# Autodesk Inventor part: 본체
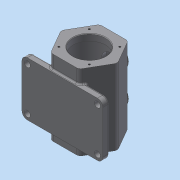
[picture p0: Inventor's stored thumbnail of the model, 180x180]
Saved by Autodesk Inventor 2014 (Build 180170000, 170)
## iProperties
Created: 2021-06
Part Number: 본체
Material: 일반
Document SubType Name: Modeling
Designer: net
Density: 1 g/cm^3
Appearance: 기본값
Author: net
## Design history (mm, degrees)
sketch "스케치2" dims "d3" = 105
  geometry: L1 (-52.5, 0)-(-26.25, 45.466); L2 (-26.25, 45.466)-(26.25, 45.466); L3 (26.25, 45.466)-(52.5, 0); L4 (52.5, 0)-(26.25, -45.466); L5 (26.25, -45.466)-(-26.25, -45.466); L6 (-26.25, -45.466)-(-52.5, 0); 4 further points
  constraints: 12 end point, 2 coincident, 1 horizontal alignment, 1 midpoint, 1 vertical alignment, 15 other
extrude "돌출1" new body sketch "스케치2" stored distance "d4" = 140; taper "d5" = 0 deg
node "작업 평면1"
sketch "스케치3"
  geometry: L1 (75, 45)-(-75, 45); L2 (-75, 45)-(-75, -55); L3 (-75, -55)-(75, -55); L4 (75, -55)-(75, 45); L5 (26.25, 70)-(52.5, 70) reference; L6 (52.5, -70)-(26.25, -70) reference; 2 further points
  constraints: 8 end point, 2 parallel, 1 horizontal, 1 midpoint, 1 perpendicular, 1 vertical alignment
  dimensions: "d7" = 25 distance between parallel lines of L1 L5; "d8" = 15 distance between parallel lines of L6 L3; "d9" = 150 distance between parallel lines of L2 L4
extrude "돌출2" join sketch "스케치3" distance "d10" = 12; taper "d11" = 0 deg
fillet "모깎기1" dims "d12" = 10
sketch "스케치4"
  geometry: C1 r 5.5 at (-65, 45); C2 r 5.5 at (-65, -35); A1 r 10 centre (-65, 45) between (-65, 55) and (-75, 45) reference; A2 r 10 centre (-65, -35) between (-75, -35) and (-65, -45) reference; 1 further point
  constraints: 2 centre point, 2 coincident
  dimensions: "d13" = 11 diameter of C1; "d14" = 11 diameter of C2
extrude "돌출3" cut sketch "스케치4" stored distance "d15" = 12; taper "d16" = 0 deg
sketch "스케치5"
  geometry: L1 (45.466, 70)-(0, 70) reference; L2 (0, 70)-(-45.466, 70) reference; L3 (-45.466, 70)-(0, 70) reference; L4 (0, 70)-(45.466, 70) reference; L5 (0, -70)-(45.466, -70) reference; L6 (45.466, -70)-(0, -70) reference; L7 (0, -70)-(-45.466, -70) reference; L8 (-45.466, -70)-(0, -70) reference; L9 (0, 70)-(30, 70); L10 (30, 58)-(37.5, 58); L11 (37.5, 58)-(37.5, -58); L12 (37.5, -58)-(30, -58); L13 (30, 58)-(30, 70); L14 (0, 70)-(0, -70); L15 (30, -58)-(30, -70); L16 (30, -70)-(0, -70); 1 further point
  constraints: 16 end point, 2 parallel, 2 perpendicular, 2 point on line
  dimensions: "d17" = 60 diameter of L13 L14; "d18" = 75 diameter of L11 L14; "d20" = 12 distance of L10.start L9.end; "d21" = 12 distance of L12.end L15.end; "d22" = 60 diameter of L15 L14; "d23" = 12 distance from line of L1 L10.end
revolve "회전1" sketch "스케치5" stored, may be unused: angle "d24" = 90 deg
sketch "스케치8"
  geometry: L1 (52.5, 0)-(26.25, 45.466) reference; L2 (26.25, 45.466)-(-26.25, 45.466) reference; L3 (0, 45.466)-(0, 0); L4 (0, 0)-(33.284, 33.284); C1 r 30 at (0, 0) reference; 1 further point
  constraints: 4 end point, 2 point on line, 1 midpoint
  dimensions: "d39" = 45 deg angle of L4 L3; "d40" = 40 distance of L3.end point (28.284, 28.284)
hole "구멍2" sketch "스케치8" at (28.284, 28.284) diameter "d41" = 3.459; stored, may be unused: countersink angle "d45" = 90 deg, drill point angle "d47" = 118 deg; dims "d42" = 8, "d43" = 4, "d44" = 2, "d46" = 10
sketch "스케치9"
  geometry: C1 r 30 at (0, 0) reference; 1 further point
  constraints: 1 vertical alignment
  dimensions: "d51" = 40 distance of C1.centre point (0, 40)
hole "구멍3" sketch "스케치9" at (0, 40) diameter "d52" = 3.459; stored, may be unused: countersink angle "d56" = 90 deg, drill point angle "d58" = 118 deg; dims "d53" = 8, "d54" = 4, "d55" = 2, "d57" = 10
node "작업 평면2"
sketch "스케치11"
  geometry: L1 (-26.25, 70)-(26.25, 70) reference; C1 r 20 at (0, 30); C2 r 20 at (0, -30); 2 further points
  constraints: 2 centre point, 2 vertical alignment, 1 midpoint
  dimensions: "d67" = 40 distance of point (0, 70) C1.centre; "d68" = 60 distance of C2.centre C1.centre; "d69" = 40 diameter of C1; "d70" = 40 diameter of C2
extrude "돌출4" join sketch "스케치11" stored distance "d71" = 12; taper "d72" = 0 deg
sketch "스케치12"
  geometry: C1 r 20 at (0, 0) reference; C2 r 15 at (0, 0); C3 r 20 at (0, 60) reference; C4 r 15 at (0, 60); 1 further point
  constraints: 2 centre point, 2 coincident
  dimensions: "d73" = 30 diameter of C2; "d74" = 30 diameter of C4
extrude "돌출5" cut sketch "스케치12" distance "d75" = 8; taper "d76" = 0 deg
sketch "스케치13"
  geometry: C1 r 15 at (0, 0) reference; C2 r 12.5 at (0, 0); C3 r 15 at (0, 60) reference; C4 r 12.5 at (0, 60); 1 further point
  constraints: 2 centre point, 2 coincident
  dimensions: "d77" = 25 diameter of C2; "d78" = 25 diameter of C4
extrude "돌출6" cut sketch "스케치13" stored distance "d79" = 8; taper "d80" = 0 deg
fillet "모깎기2" dims "d81" = 8
fillet "모깎기3" dims "d82" = 3
fillet "모깎기4" dims "d83" = 3
chamfer "모따기1" distance "d85" = 1; stored, may be unused: second distance "d86" = 2, angle "d87" = 45 deg
sketch "스케치14"
  geometry: L1 (-65, -45)-(-32.293, -45) reference; L2 (-75, 45)-(-75, -35) reference; 2 further points
  constraints: 1 other
  dimensions: "d88" = 50 distance from line of L1 point (-61, 5); "d89" = 14 distance from line of L2 point (-61, 5)
feature "엠보싱1" sketch "스케치14" dims "d90" = 0.5, "d91" = 0
fillet "모깎기6" dims "d92" = 5
fillet "모깎기7" dims "d93" = 3
node "솔리드1"
mirror "대칭1"
pattern_circular "원형 패턴2" dims angle "d49" = 360 deg
pattern_circular "원형 패턴3" dims angle "d60" = 360 deg
node "투영된 루프1"
node "투영된 루프2"
other parameters: "d66" = 52.5
